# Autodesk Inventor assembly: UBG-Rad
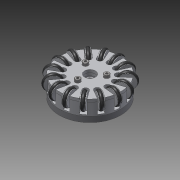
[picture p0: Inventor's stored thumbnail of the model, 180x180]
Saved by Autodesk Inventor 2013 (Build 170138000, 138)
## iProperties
Created: 2012-07
Part Number: UBG-Rad
Document SubType Name: Assembly
Designer: rYan
Mass: 102.562 g
Surface Area: 311.765 cm^2
Volume: 34.8609 cm^3
Density: 2.94203 g/cm^3
Author: rYan
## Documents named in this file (10)
- D:\SVN\2013\Inventor\Antrieb\UBG-Rad.iam
- D:\SVN\2013\Inventor\Antrieb\Radkasten.ipt
- D:\SVN\2013\Inventor\Antrieb\MG-Rolle mit Achse.iam
- D:\SVN\2013\Inventor\Inhaltscenter\de-DE\DIN BEARING(1)\DIN 625 SKF - SKF 627.ipt
- D:\SVN\2013\Inventor\Antrieb\Raddeckel.ipt
- D:\SVN\2013\Inventor\Antrieb\PH-Radaussenvisualisierung.ipt
- D:\SVN\2013\Inventor\Kaufteile\Innenzahnrad z50.ipt
- D:\SVN\2013\Inventor\Antrieb\Radwelle.ipt
- D:\SVN\2013\Inventor\Inhaltscenter\de-DE\ISO 4762(1)\ISO 4762 - M2 x 4DIN EN ISO.ipt
- D:\SVN\2013\Inventor\Inhaltscenter\de-DE\DIN ISO 8734(1)\ISO 8734 - 3 x 8 - ADIN EN.ipt
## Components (27 placed, 9 different names)
1. Radkasten:1 — Passend:1, Passend:2, Passend:3, Passend:5, Fluchtend:1, Passend:6, Passend:7, Passend:8, Passend:9, Passend:16, Passend:17, Passend:18
2. DIN 625 SKF 627:1 — Passend:5, Passend:10, Fluchtend:2
3. Raddeckel:1 — Fluchtend:1, Passend:12, Passend:17, Passend:18
4. PH-Radaußenvisualisierung:1 — Passend:6, Passend:16
5. Innenzahnrad z=50:1 — Passend:7, Passend:8, Passend:9, Passend:13, Passend:14, Passend:15, Fluchtend:3, Fluchtend:4, Fluchtend:5
6. Radwelle:1 — Passend:10, Fluchtend:2
7. DIN EN ISO 8734 3 x 8 - A:1 — Passend:13, Fluchtend:4
8. DIN EN ISO 8734 3 x 8 - A:2 — Passend:14, Fluchtend:3
9. DIN EN ISO 8734 3 x 8 - A:3 — Passend:15, Fluchtend:5
10. MG-Rolle mit Achse:1 [sub-assembly] — Passend:1, Passend:2, Passend:3
11. MG-Rolle mit Achse:2 [sub-assembly]
12. MG-Rolle mit Achse:3 [sub-assembly]
13. MG-Rolle mit Achse:4 [sub-assembly]
14. MG-Rolle mit Achse:5 [sub-assembly]
15. MG-Rolle mit Achse:6 [sub-assembly]
16. MG-Rolle mit Achse:7 [sub-assembly]
17. MG-Rolle mit Achse:8 [sub-assembly]
18. MG-Rolle mit Achse:9 [sub-assembly]
19. MG-Rolle mit Achse:10 [sub-assembly]
20. MG-Rolle mit Achse:11 [sub-assembly]
21. MG-Rolle mit Achse:12 [sub-assembly]
22. MG-Rolle mit Achse:13 [sub-assembly]
23. MG-Rolle mit Achse:14 [sub-assembly]
24. MG-Rolle mit Achse:15 [sub-assembly]
25. DIN EN ISO 4762 M2 x 4:1 — Passend:12
26. DIN EN ISO 4762 M2 x 4:2
27. DIN EN ISO 4762 M2 x 4:3
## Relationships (21: Mate 16, Flush 5)
- Passend:1 [Mate]: Radkasten:1 ↔ MG-Rolle mit Achse:1
- Passend:2 [Mate]: Radkasten:1 ↔ MG-Rolle mit Achse:1
- Passend:3 [Mate]: Radkasten:1 ↔ MG-Rolle mit Achse:1
- Passend:5 [Mate]: Radkasten:1 ↔ DIN 625 SKF 627:1
- Fluchtend:1 [Flush]: Radkasten:1 ↔ Raddeckel:1
- Passend:6 [Mate]: Radkasten:1 ↔ PH-Radaußenvisualisierung:1
- Passend:7 [Mate]: Radkasten:1 ↔ Innenzahnrad z=50:1
- Passend:8 [Mate]: Radkasten:1 ↔ Innenzahnrad z=50:1
- Passend:9 [Mate]: Radkasten:1 ↔ Innenzahnrad z=50:1
- Passend:10 [Mate]: DIN 625 SKF 627:1 ↔ Radwelle:1
- Fluchtend:2 [Flush]: DIN 625 SKF 627:1 ↔ Radwelle:1
- Passend:12 [Mate]: Raddeckel:1 ↔ DIN EN ISO 4762 M2 x 4:1
- Passend:13 [Mate]: Innenzahnrad z=50:1 ↔ DIN EN ISO 8734 3 x 8 - A:1
- Passend:14 [Mate]: Innenzahnrad z=50:1 ↔ DIN EN ISO 8734 3 x 8 - A:2
- Passend:15 [Mate]: Innenzahnrad z=50:1 ↔ DIN EN ISO 8734 3 x 8 - A:3
- Fluchtend:3 [Flush]: Innenzahnrad z=50:1 ↔ DIN EN ISO 8734 3 x 8 - A:2
- Fluchtend:4 [Flush]: Innenzahnrad z=50:1 ↔ DIN EN ISO 8734 3 x 8 - A:1
- Fluchtend:5 [Flush]: Innenzahnrad z=50:1 ↔ DIN EN ISO 8734 3 x 8 - A:3
- Passend:16 [Mate]: Radkasten:1 ↔ PH-Radaußenvisualisierung:1
- Passend:17 [Mate]: Radkasten:1 ↔ Raddeckel:1
- Passend:18 [Mate]: Radkasten:1 ↔ Raddeckel:1
